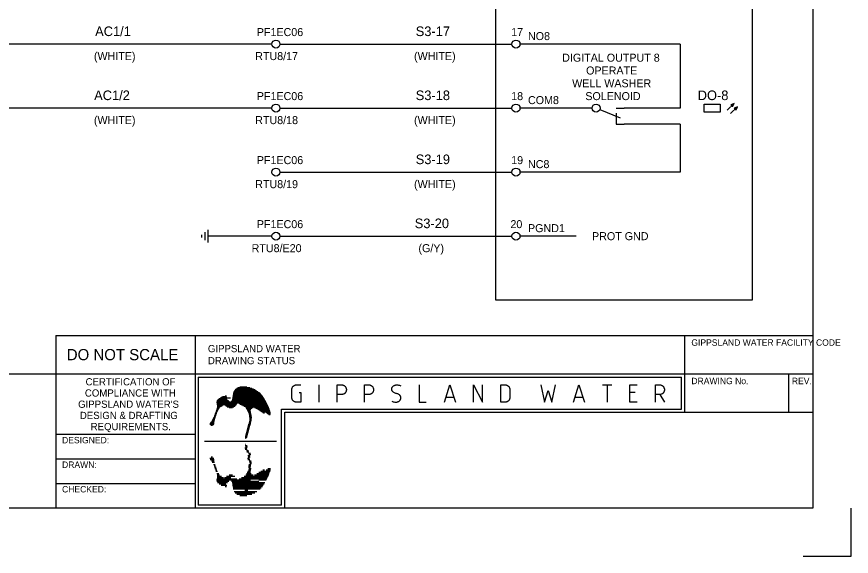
# Model space of a CAD drawing. Extents: x 0 to 841, y 0 to 594.
# Drawn here: x 580.3 to 841, y 0 to 168.6 of the extents above; entities that cross this region are included whole.
import ezdxf

# ---------------------------------------------------------------- set-up
doc = ezdxf.new("R2010")
doc.units = 0
for name, color, linetype in [('A1BORDER', 7, 'Continuous'), ('Level 1', 7, 'Continuous'), ('Level 10', 7, 'Continuous')]:
    doc.layers.add(name, color=color, linetype=linetype)

msp = doc.modelspace()

# ---------------------------------------------------------------- linework, layer by layer
at = {"layer": 'A1BORDER'}
for p, q in [((829, 581), (829, 15)), ((592.5, 69), (592.5, 15)), ((592.5, 69), (829, 69)), ((636, 69), (636, 15)), ((789, 45), (789, 69)), ((28, 57), (829, 57)), ((637, 56), (788, 56)), ((637, 56), (637, 16)), ((788, 46), (788, 56)), ((821.5, 45), (821.5, 57)), ((648.74, 52.32), (654.24, 52.32)), ((649.02, 52.52), (653.76, 52.52)), ((649.39, 52.72), (653.15, 52.72)), ((650.01, 52.92), (652.2, 52.92)), ((644.18, 49.72), (645.89, 49.72)), ((644.54, 49.92), (645.36, 49.92)), ((645.37, 50.12), (645.86, 50.12)), ((647.71, 49.72), (657.31, 49.72)), ((647.75, 49.92), (657.17, 49.92)), ((647.78, 50.12), (657.02, 50.12)), ((647.81, 50.32), (656.86, 50.32)), ((647.85, 50.52), (656.69, 50.52)), ((647.88, 50.72), (656.5, 50.72)), ((647.91, 50.92), (656.3, 50.92)), ((647.96, 51.12), (656.08, 51.12)), ((648.03, 51.32), (655.85, 51.32)), ((648.12, 51.52), (655.59, 51.52)), ((648.23, 51.72), (655.31, 51.72)), ((648.37, 51.92), (655, 51.92)), ((648.53, 52.12), (654.64, 52.12)), ((642.73, 48.12), (658.25, 48.12)), ((642.74, 47.92), (658.35, 47.92)), ((642.75, 48.32), (646.79, 48.32)), ((642.79, 47.72), (649.08, 47.72)), ((642.81, 48.52), (646.55, 48.52)), ((642.83, 47.52), (648.95, 47.52)), ((642.85, 47.31), (644.88, 47.31)), ((642.87, 47.12), (644.57, 47.12)), ((642.9, 48.72), (646.37, 48.72)), ((643.04, 48.92), (646.16, 48.92)), ((643.26, 49.12), (645.9, 49.12)), ((643.54, 49.32), (645.57, 49.32)), ((643.85, 49.52), (647.09, 49.52)), ((645.14, 47.31), (648.83, 47.31)), ((645.49, 47.12), (648.67, 47.12)), ((647.19, 48.32), (658.14, 48.32)), ((647.42, 48.52), (658.03, 48.52)), ((647.54, 48.72), (657.92, 48.72)), ((647.61, 48.92), (657.8, 48.92)), ((647.63, 49.12), (657.68, 49.12)), ((647.66, 49.32), (657.57, 49.32)), ((647.69, 49.52), (657.44, 49.52)), ((649.72, 47.72), (658.45, 47.72)), ((650.12, 47.52), (658.55, 47.52)), ((650.48, 47.31), (658.64, 47.31)), ((650.87, 47.12), (658.73, 47.12)), ((642.21, 44.52), (642.69, 44.52)), ((642.28, 44.72), (642.76, 44.72)), ((642.35, 44.92), (642.83, 44.92)), ((642.43, 45.12), (642.9, 45.12)), ((642.5, 45.32), (643, 45.32)), ((642.57, 45.52), (643.1, 45.52)), ((642.65, 45.72), (643.2, 45.72)), ((642.72, 45.92), (643.3, 45.92)), ((642.79, 46.12), (643.4, 46.12)), ((642.84, 46.32), (643.5, 46.32)), ((642.87, 46.52), (643.6, 46.52)), ((642.88, 46.92), (644.23, 46.92)), ((642.88, 46.72), (643.83, 46.72)), ((645.76, 46.92), (648.42, 46.92)), ((646.05, 46.72), (648.11, 46.72)), ((646.62, 46.52), (647.67, 46.52)), ((651.36, 46.92), (658.82, 46.92)), ((651.76, 46.72), (658.9, 46.72)), ((651.88, 46.52), (654.15, 46.52)), ((651.99, 46.32), (653.71, 46.32)), ((652.1, 46.12), (653.52, 46.12)), ((652.2, 45.92), (653.4, 45.92)), ((652.31, 45.72), (653.33, 45.72)), ((652.41, 45.52), (653.31, 45.52)), ((652.5, 45.32), (653.34, 45.32)), ((652.6, 45.12), (653.38, 45.12)), ((652.69, 44.92), (653.41, 44.92)), ((652.78, 44.72), (653.44, 44.72)), ((652.83, 44.52), (653.48, 44.52)), ((654.57, 46.52), (658.99, 46.52)), ((655, 46.32), (659.07, 46.32)), ((655.31, 46.12), (659.14, 46.12)), ((655.62, 45.92), (659.22, 45.92)), ((655.93, 45.72), (659.29, 45.72)), ((656.24, 45.52), (659.35, 45.52)), ((656.55, 45.32), (659.42, 45.32)), ((656.86, 45.12), (657.74, 45.12)), ((657.17, 44.92), (657.68, 44.92)), ((657.51, 44.72), (657.54, 44.72)), ((657.91, 45.12), (659.48, 45.12)), ((658.19, 44.92), (659.54, 44.92)), ((658.47, 44.72), (659.59, 44.72)), ((658.75, 44.52), (659.58, 44.52)), ((663, 46), (788, 46)), ((663, 16), (663, 46)), ((664, 45), (829, 45)), ((664, 15), (664, 45)), ((640.73, 41.72), (641.95, 41.72)), ((640.9, 41.92), (641.97, 41.92)), ((641.1, 42.12), (642, 42.12)), ((641.25, 42.31), (642.04, 42.31)), ((641.37, 42.52), (642.09, 42.52)), ((641.46, 42.72), (642.15, 42.72)), ((641.55, 42.92), (642.2, 42.92)), ((641.64, 43.12), (642.25, 43.12)), ((641.73, 43.32), (642.3, 43.32)), ((641.82, 43.51), (642.35, 43.51)), ((641.91, 43.72), (642.41, 43.72)), ((641.99, 43.92), (642.48, 43.92)), ((642.06, 44.12), (642.55, 44.12)), ((642.13, 44.32), (642.62, 44.32)), ((652.79, 41.72), (653.41, 41.72)), ((652.85, 41.92), (653.45, 41.92)), ((652.86, 44.32), (653.53, 44.32)), ((652.89, 44.12), (653.57, 44.12)), ((652.9, 42.12), (653.49, 42.12)), ((652.91, 43.92), (653.62, 43.92)), ((652.94, 43.72), (653.67, 43.72)), ((652.95, 42.31), (653.53, 42.31)), ((652.97, 43.51), (653.71, 43.51)), ((652.99, 42.52), (653.57, 42.52)), ((653, 43.32), (653.69, 43.32)), ((653.02, 43.12), (653.67, 43.12)), ((653.03, 42.72), (653.61, 42.72)), ((653.05, 42.92), (653.64, 42.92)), ((659.02, 44.32), (659.47, 44.32)), ((640.62, 41.32), (641.88, 41.32)), ((640.63, 41.52), (641.93, 41.52)), ((640.72, 41.12), (641.73, 41.12)), ((641.03, 40.92), (641.43, 40.92)), ((652.09, 39.12), (652.72, 39.12)), ((652.14, 39.32), (652.77, 39.32)), ((652.2, 39.52), (652.82, 39.52)), ((652.25, 39.72), (652.88, 39.72)), ((652.3, 39.92), (652.93, 39.92)), ((652.36, 40.12), (652.99, 40.12)), ((652.41, 40.32), (653.04, 40.32)), ((652.47, 40.52), (653.1, 40.52)), ((652.52, 40.72), (653.15, 40.72)), ((652.57, 40.92), (653.2, 40.92)), ((652.63, 41.12), (653.26, 41.12)), ((652.68, 41.32), (653.31, 41.32)), ((652.74, 41.52), (653.37, 41.52)), ((636, 38), (592.5, 38)), ((651.63, 37.32), (652.23, 37.32)), ((651.64, 37.12), (652.17, 37.12)), ((651.65, 37.52), (652.28, 37.52)), ((651.71, 37.72), (652.34, 37.72)), ((651.76, 37.92), (652.39, 37.92)), ((651.79, 36.92), (651.9, 36.92)), ((651.82, 38.12), (652.44, 38.12)), ((651.87, 38.32), (652.5, 38.32)), ((651.92, 38.52), (652.55, 38.52)), ((651.98, 38.72), (652.61, 38.72)), ((652.03, 38.92), (652.66, 38.92)), ((638.93, 35.98), (661.47, 35.98)), ((651.63, 34.64), (652.23, 34.64)), ((651.71, 34.24), (652.34, 34.24)), ((651.79, 35.04), (651.9, 35.04)), ((651.54, 33.84), (652.17, 33.84)), ((651.65, 33.44), (652.28, 33.44)), ((652.03, 33.04), (652.66, 33.04)), ((652.14, 32.64), (652.77, 32.64)), ((652.47, 31.44), (653.1, 31.44)), ((652.66, 32.24), (653.29, 32.24)), ((652.77, 31.84), (653.4, 31.84)), ((636, 30.34), (592.5, 30.34)), ((640.62, 30.64), (641.88, 30.64)), ((640.73, 30.24), (641.95, 30.24)), ((641.03, 31.04), (641.43, 31.04)), ((641.1, 29.84), (642, 29.84)), ((641.37, 29.44), (642.09, 29.44)), ((652.34, 30.64), (652.97, 30.64)), ((652.45, 30.24), (653.07, 30.24)), ((652.57, 31.04), (653.2, 31.04)), ((652.9, 29.84), (653.49, 29.84)), ((652.99, 29.44), (653.57, 29.44)), ((653.05, 29.04), (653.64, 29.04)), ((641.73, 28.64), (642.3, 28.64)), ((641.91, 28.24), (642.41, 28.24)), ((642.06, 27.84), (642.55, 27.84)), ((642.21, 27.44), (642.69, 27.44)), ((642.35, 27.04), (642.83, 27.04)), ((642.5, 26.64), (643, 26.64)), ((652.31, 26.24), (653.33, 26.24)), ((652.5, 26.64), (653.34, 26.64)), ((652.66, 27.84), (653.35, 27.84)), ((652.69, 27.04), (653.41, 27.04)), ((652.72, 28.24), (653.44, 28.24)), ((652.77, 28.64), (653.46, 28.64)), ((652.83, 27.44), (653.48, 27.44)), ((655.93, 26.24), (659.29, 26.24)), ((656.55, 26.64), (659.42, 26.64)), ((657.17, 27.04), (657.68, 27.04)), ((658.19, 27.04), (659.54, 27.04)), ((658.75, 27.44), (659.58, 27.44)), ((642.73, 23.84), (653.27, 23.84)), ((642.79, 25.84), (643.4, 25.84)), ((642.79, 24.24), (649.08, 24.24)), ((642.85, 24.65), (644.88, 24.65)), ((642.87, 25.44), (643.6, 25.44)), ((642.88, 25.04), (644.23, 25.04)), ((645.14, 24.65), (647.18, 24.65)), ((645.76, 25.04), (648.42, 25.04)), ((646.62, 25.44), (647.67, 25.44)), ((649.72, 24.24), (658.45, 24.24)), ((650.48, 24.65), (658.64, 24.65)), ((651.36, 25.04), (658.82, 25.04)), ((651.88, 25.44), (654.15, 25.44)), ((652.1, 25.84), (653.52, 25.84)), ((654.57, 25.44), (658.99, 25.44)), ((655.31, 25.84), (659.14, 25.84)), ((655.94, 23.84), (658.25, 23.84)), ((636, 22.67), (592.5, 22.67)), ((642.81, 23.44), (646.55, 23.44)), ((643.04, 23.04), (646.16, 23.04)), ((643.54, 22.64), (645.57, 22.64)), ((644.18, 22.24), (645.89, 22.24)), ((645.37, 21.84), (645.86, 21.84)), ((647.42, 23.44), (655.89, 23.44)), ((647.61, 23.04), (657.8, 23.04)), ((647.66, 22.64), (657.57, 22.64)), ((647.71, 22.24), (657.31, 22.24)), ((647.78, 21.84), (657.02, 21.84)), ((647.85, 21.44), (656.69, 21.44)), ((647.91, 21.04), (656.3, 21.04)), ((648.23, 20.24), (655.31, 20.24)), ((648.53, 19.84), (654.64, 19.84)), ((649.02, 19.44), (653.76, 19.44)), ((650.01, 19.04), (652.2, 19.04)), ((651.57, 20.64), (652.44, 20.64)), ((663, 16), (637, 16)), ((829, 15), (28, 15)), ((829, 15), (829, 15)), ((841, 0), (841, 15)), ((826, 0), (841, 0))]:
    msp.add_line(p, q, dxfattribs=at)
for points in [[(668.49, 51.15), (669.06, 51.15), (669.06, 48.16), (667.64, 48.16), (667.51, 48.16), (667.39, 48.18), (667.28, 48.21), (667.15, 48.25), (667.04, 48.3), (666.93, 48.36), (666.82, 48.43), (666.73, 48.51), (666.64, 48.6), (666.55, 48.7), (666.48, 48.8), (666.41, 48.91), (666.35, 49.02), (666.31, 49.14), (666.27, 49.27), (666.24, 49.39), (666.22, 49.52), (666.22, 49.66), (666.22, 52.05), (666.22, 52.18), (666.24, 52.31), (666.27, 52.43), (666.31, 52.56), (666.35, 52.67), (666.41, 52.79), (666.48, 52.9), (666.55, 53), (666.64, 53.1), (666.73, 53.19), (666.82, 53.27), (666.93, 53.34), (667.04, 53.4), (667.15, 53.45), (667.28, 53.49), (667.39, 53.52), (667.51, 53.54), (667.64, 53.54), (669.06, 53.54)], [(674.74, 48.16), (674.74, 53.54)], [(680.42, 48.16), (680.42, 53.54), (681.84, 53.54), (681.96, 53.54), (682.08, 53.52), (682.2, 53.49), (682.32, 53.45), (682.43, 53.4), (682.54, 53.34), (682.65, 53.27), (682.74, 53.19), (682.84, 53.1), (682.92, 53), (682.99, 52.9), (683.06, 52.79), (683.12, 52.67), (683.17, 52.56), (683.21, 52.43), (683.23, 52.31), (683.25, 52.18), (683.26, 52.05), (683.25, 51.91), (683.23, 51.78), (683.21, 51.66), (683.17, 51.53), (683.12, 51.42), (683.06, 51.3), (682.99, 51.19), (682.92, 51.09), (682.84, 50.99), (682.74, 50.9), (682.65, 50.82), (682.54, 50.75), (682.43, 50.69), (682.32, 50.64), (682.2, 50.6), (682.08, 50.57), (681.96, 50.55), (681.84, 50.55), (680.42, 50.55)], [(688.93, 48.16), (688.93, 53.54), (690.35, 53.54), (690.47, 53.54), (690.59, 53.52), (690.71, 53.49), (690.83, 53.45), (690.94, 53.4), (691.05, 53.34), (691.16, 53.27), (691.26, 53.19), (691.35, 53.1), (691.43, 53), (691.51, 52.9), (691.57, 52.79), (691.63, 52.67), (691.68, 52.56), (691.72, 52.43), (691.75, 52.31), (691.76, 52.18), (691.77, 52.05), (691.76, 51.91), (691.75, 51.78), (691.72, 51.66), (691.68, 51.53), (691.63, 51.42), (691.57, 51.3), (691.51, 51.19), (691.43, 51.09), (691.35, 50.99), (691.26, 50.9), (691.16, 50.82), (691.05, 50.75), (690.94, 50.69), (690.83, 50.64), (690.71, 50.6), (690.59, 50.57), (690.47, 50.55), (690.35, 50.55), (688.93, 50.55)], [(697.45, 48.46), (697.67, 48.36), (697.9, 48.27), (698.12, 48.21), (698.36, 48.17), (698.6, 48.16), (698.84, 48.16), (698.87, 48.16), (699.03, 48.18), (699.18, 48.21), (699.33, 48.26), (699.48, 48.32), (699.62, 48.4), (699.72, 48.46), (699.81, 48.53), (699.9, 48.61), (699.98, 48.69), (700.05, 48.78), (700.11, 48.88), (700.17, 48.99), (700.22, 49.09), (700.25, 49.21), (700.28, 49.32), (700.29, 49.36), (700.3, 49.44), (700.3, 49.52), (700.3, 49.61), (700.29, 49.69), (700.27, 49.77), (700.25, 49.86), (700.22, 49.93), (700.18, 50.01), (700.14, 50.09), (700.09, 50.15), (700.04, 50.21), (700.01, 50.25), (699.85, 50.39), (699.69, 50.51), (699.52, 50.61), (699.34, 50.7), (699.15, 50.78), (698.95, 50.83), (698.87, 50.85), (698.68, 50.9), (698.49, 50.96), (698.3, 51.04), (698.12, 51.14), (697.96, 51.26), (697.8, 51.39), (697.73, 51.45), (697.67, 51.51), (697.62, 51.57), (697.58, 51.64), (697.53, 51.71), (697.5, 51.79), (697.47, 51.87), (697.46, 51.95), (697.44, 52.04), (697.43, 52.12), (697.43, 52.21), (697.44, 52.29), (697.45, 52.35), (697.47, 52.46), (697.51, 52.58), (697.55, 52.69), (697.61, 52.79), (697.67, 52.89), (697.74, 52.99), (697.82, 53.07), (697.9, 53.15), (697.99, 53.23), (698.02, 53.24), (698.15, 53.33), (698.3, 53.4), (698.44, 53.45), (698.6, 53.5), (698.75, 53.52), (698.87, 53.54), (699.11, 53.55), (699.35, 53.53), (699.58, 53.49), (699.82, 53.43), (700.04, 53.35), (700.27, 53.25)], [(705.96, 53.54), (705.96, 48.16), (708.23, 48.16)], [(713.91, 48.16), (715.61, 53.54), (717.32, 48.16)], [(722.99, 48.16), (722.99, 53.54), (725.83, 48.16), (725.83, 53.54)], [(731.52, 48.16), (731.52, 53.54), (732.94, 53.54), (733.06, 53.54), (733.18, 53.52), (733.3, 53.49), (733.42, 53.45), (733.53, 53.4), (733.64, 53.34), (733.75, 53.27), (733.84, 53.19), (733.94, 53.1), (734.02, 53), (734.09, 52.9), (734.16, 52.79), (734.22, 52.67), (734.27, 52.56), (734.31, 52.43), (734.33, 52.31), (734.35, 52.18), (734.36, 52.05), (734.36, 49.66), (734.35, 49.52), (734.33, 49.39), (734.31, 49.27), (734.27, 49.14), (734.22, 49.02), (734.16, 48.91), (734.09, 48.8), (734.02, 48.7), (733.94, 48.6), (733.84, 48.51), (733.75, 48.43), (733.64, 48.36), (733.53, 48.3), (733.42, 48.25), (733.3, 48.21), (733.18, 48.18), (733.06, 48.16), (732.94, 48.16), (731.52, 48.16)], [(744.01, 53.54), (745.14, 48.16), (746.28, 51.75), (747.41, 48.16), (748.55, 53.54)], [(754.22, 48.16), (755.92, 53.54), (757.63, 48.16)], [(763.31, 53.54), (766.15, 53.54)], [(764.73, 53.54), (764.73, 48.16)], [(774.09, 48.16), (771.82, 48.16), (771.82, 53.54), (774.09, 53.54)], [(779.78, 48.16), (779.78, 53.54), (781.2, 53.54), (781.32, 53.54), (781.44, 53.52), (781.56, 53.49), (781.68, 53.45), (781.79, 53.4), (781.9, 53.34), (782.01, 53.27), (782.1, 53.19), (782.2, 53.1), (782.28, 53), (782.35, 52.9), (782.42, 52.79), (782.48, 52.67), (782.53, 52.56), (782.56, 52.43), (782.59, 52.31), (782.61, 52.18), (782.61, 52.05), (782.61, 51.91), (782.59, 51.78), (782.56, 51.66), (782.53, 51.53), (782.48, 51.42), (782.42, 51.3), (782.35, 51.19), (782.28, 51.09), (782.2, 50.99), (782.1, 50.9), (782.01, 50.82), (781.9, 50.75), (781.79, 50.69), (781.68, 50.64), (781.56, 50.6), (781.44, 50.57), (781.32, 50.55), (781.2, 50.55), (779.78, 50.55)], [(714.48, 49.66), (716.75, 49.66)], [(754.79, 49.66), (757.06, 49.66)], [(773.53, 51.15), (771.82, 51.15)], [(781.2, 50.55), (782.61, 48.16)]]:
    msp.add_lwpolyline(points, dxfattribs=at)
at = {"layer": 'Level 1'}
for p, q in [((660, 160), (360, 160)), ((662.5, 160), (735, 160)), ((787.5, 160), (737.5, 160)), ((787.5, 160), (787.5, 140)), ((660, 140), (360, 140)), ((662.5, 140), (735, 140)), ((760, 140), (737.5, 140)), ((787.5, 140), (770, 140)), ((787.5, 135), (770, 135)), ((787.5, 135), (787.5, 120)), ((662.5, 120), (735, 120)), ((787.5, 120), (737.5, 120)), ((660, 100), (640, 100)), ((662.5, 100), (735, 100)), ((755, 100), (737.5, 100))]:
    msp.add_line(p, q, dxfattribs=at)
for points in [[(730, 540), (810, 540), (810, 80), (730, 80)], [(795, 141.25), (800, 141.25), (800, 138.75), (795, 138.75)]]:
    msp.add_lwpolyline(points, close=True, dxfattribs=at)
for centre in [(661.25, 160), (736.25, 160), (661.25, 140), (736.25, 140), (661.25, 120), (736.25, 120), (661.25, 100), (736.25, 100)]:
    msp.add_circle(centre, 1.25, dxfattribs=at)
at = {"layer": 'Level 10'}
for p, q in [((802.23, 139.35), (804.36, 141.48)), ((803.46, 141.08), (804.17, 141.08)), ((803.5, 140.93), (804.11, 140.93)), ((803.79, 141.22), (804.24, 141.22)), ((804.12, 141.38), (804.31, 141.38)), ((762.41, 139.54), (768.75, 137)), ((767.5, 140), (770, 140)), ((767.5, 138.37), (767.5, 135)), ((803.29, 138.3), (805.41, 140.42)), ((803.64, 140.78), (804.03, 140.78)), ((803.8, 140.62), (803.97, 140.62)), ((804.52, 140.02), (805.23, 140.02)), ((804.56, 139.87), (805.16, 139.87)), ((804.71, 139.72), (805.1, 139.72)), ((804.85, 140.16), (805.3, 140.16)), ((804.86, 139.56), (805.03, 139.56)), ((805.18, 140.31), (805.37, 140.31)), ((767.5, 135), (770, 135)), ((640, 102), (640, 98)), ((638, 100.4), (638, 99.6)), ((639, 101.2), (639, 98.8))]:
    msp.add_line(p, q, dxfattribs=at)
for points in [[(804.36, 141.48), (803.38, 141.04), (803.91, 140.5)], [(805.41, 140.42), (804.44, 139.98), (804.98, 139.44)]]:
    msp.add_lwpolyline(points, close=True, dxfattribs=at)
msp.add_circle((761.25, 140), 1.25, dxfattribs=at)

# ---------------------------------------------------------------- texts
at = {"layer": 'A1BORDER'}
for s, height, p in [('GIPPSLAND WATER FACILITY CODE', 2, (791.03, 65.77)), ('GIPPSLAND WATER', 2.25, (640, 63.75)), ('DO NOT SCALE', 3.5, (595.92, 61.25)), ('DRAWING STATUS', 2.25, (640, 60)), ('CERTIFICATION OF', 2.25, (601.79, 53.39)), ('DRAWING No.', 2, (791.03, 53.77)), ('REV.', 2, (822.43, 53.77)), ('COMPLIANCE WITH', 2.25, (601.57, 49.89)), ("GIPPSLAND WATER'S", 2.25, (599.45, 46.39)), ('DESIGN & DRAFTING', 2.25, (600, 42.89)), ('REQUIREMENTS.', 2.25, (603.37, 39.39)), ('DESIGNED:', 2, (594.44, 35.29)), ('DRAWN:', 2, (594.44, 27.62)), ('CHECKED:', 2, (594.44, 19.95))]:
    msp.add_text(s, height=height, dxfattribs=at).set_placement(p)
at = {"layer": 'Level 1'}
for s, height, p in [('AC1/1', 3, (604.78, 162.5)), ('PF1EC06', 2.5, (655.28, 162.5)), ('S3-17', 3, (704.93, 162.5)), ('17', 2.5, (734.75, 162.5)), ('NO8', 2.5, (740, 161.25)), ('(WHITE)', 2.5, (604.39, 155)), ('RTU8/17', 2.5, (654.78, 155)), ('(WHITE)', 2.5, (704.4, 155)), ('DIGITAL OUTPUT 8', 2.5, (750.68, 154.5)), ('OPERATE', 2.5, (758.15, 150.5)), ('WELL WASHER', 2.5, (753.79, 146.5)), ('AC1/2', 3, (604.47, 142.5)), ('PF1EC06', 2.5, (655.28, 142.5)), ('S3-18', 3, (704.93, 142.5)), ('18', 2.5, (734.75, 142.5)), ('COM8', 2.5, (740, 141.25)), ('SOLENOID', 2.5, (757.9, 142.5)), ('DO-8', 3, (793.02, 142.5)), ('(WHITE)', 2.5, (604.39, 135)), ('RTU8/18', 2.5, (654.78, 135)), ('(WHITE)', 2.5, (704.4, 135)), ('S3-19', 3, (704.93, 122.5)), ('PF1EC06', 2.5, (655.28, 122.5)), ('19', 2.5, (734.75, 122.5)), ('NC8', 2.5, (740, 121.25)), ('RTU8/19', 2.5, (654.78, 115)), ('(WHITE)', 2.5, (704.4, 115)), ('PF1EC06', 2.5, (655.28, 102.5)), ('S3-20', 3, (704.62, 102.5)), ('20', 2.5, (734.51, 102.5)), ('PGND1', 2.5, (740, 101.25)), ('PROT GND', 2.5, (760, 98.75)), ('RTU8/E20', 2.5, (653.66, 95)), ('(G/Y)', 2.5, (705.77, 95))]:
    msp.add_text(s, height=height, dxfattribs=at).set_placement(p)

doc.saveas('drawing.dxf')
